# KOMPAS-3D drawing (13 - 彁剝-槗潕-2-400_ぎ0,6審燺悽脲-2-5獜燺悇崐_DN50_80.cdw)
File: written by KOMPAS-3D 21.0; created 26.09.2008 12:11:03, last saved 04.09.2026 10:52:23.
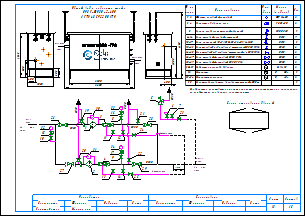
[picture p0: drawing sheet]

Sheets 1-2: A3, landscape

Document properties: Наименование: Макро:21; Автор: RaskoAdmin; Форматы листов документа: 2xA3; Полное имя файла: \\UR38nt01\Departments\КТО\КБ ПУРДГ\Заявки\Прайс-лист на типовые шкафы ГРПШ\ПРДГ_стандарт_20_03_2026\ПРДГ с РДНК\ПРДГ-ШУЭО-2-400_до0,6МПа_Рвых-2-5кПа_РДНК_DN50_80.cdw

Title block, sheet 1: Наименование: Пункт учета газа / ПУГ-Ш-400-Р / ЛГТИ.485922.001ТУ; designation: ЛГТИ.03.4411141; sheet number: 1; Количество листов документа: 2; organisation: ООО "ЭЛЬСТЕР Газэлектроника"; Форматы листов документа: A3; stored path: C:\Рабочие документы\Компас\ПУГ\Схема.cdw; Разработал: Устинов; Проверил: Кошкин; Утвердил: Кошкин
Title block, sheet 2: sheet number: 2; stored path: D:\Рабочие документы\Заявки\ПУРДГ\ПУРДГ-ШУЭО-2-100-Р 4411220.cdw; designation, second copy: ЛГТИ.03.4411141-

Views: Вид 1, Вид 2
Referenced files: wcvoit.frw
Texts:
  Normal
  Вход
  газа
  PDI
  Выход
  Р=     кПа
  DN80
  DN50
  DN20
  Импульс DN15
  ≥5DN
  HYSWLongFangSong
  № на
  схеме
  Усл.
  обозн.
  Марка
  (модель)
  Кол.
  Фильтр газовый фланцевый
  ФГ 16-50
  Регулятор давления газа
  РДНК-50
  Клапан предохранительный сбросной
  КПС DN20
  Кран шаровой газовый латунный
  DN15
  Кран кнопочный VE-РАСКО-НЗ-1,6-G1/2-М20
  Кран шаровой "под приварку" штуцерный DN20 PN16
  Кран шаровой "под приварку" штуцерный п/п DN15 PN16
  Кран шаровой фланцевый DN50 PN16
  Кран шаровой фланцевый DN80 PN16
  Индикатор перепада давления
  Delta 15
  Манометр
  Манометр-напоромер
  Электрообогреватель взрывозащищенный 400Вт
  0...     МПа
  0...     кПа
  Общий вид и габариты шкафа
  ПРДГ-ШУЭО-2-400
  Выход газа
  Вход газа
  Схема открывания дверей
  Р=        МПа
  logo-rasko-ge.png
  Предприятие изготовитель может заменять комплектующие на аналогичные,
  не ухудшающие заявленных характеристик.
  Должность
  Конструктор
  Фамилия
  Подпись
  Дата
  Согласовано
  Максимкин
  Лист
  Листов
  POLYLINE_STYLE_0.18_RGB_0_0_0
  POLYLINE_STYLE_0.50_RGB_0_0_0
  POLYLINE_STYLE_0.34_RGB_0_0_0
  PHANTOM_RGB_0_0_0_SC_1_THICK_0.18
  K5LT_THIN_RGB_0_0_0_THICK_0.18
  K5LT32769_RGB_0_0_0_THICK_0.18
  K5LT12_RGB_0_0_0_SC_1_THICK_0.18
  K5LT_DASHED_RGB_0_0_0_SC_1_THICK_0.18
  ACISOTGL_RGB_0_0_0_SC_0.8_THICK_0.25
  CONTINUOUS_RGB_0_127_31_THICK_0.3
  CONTINUOUS_RGB_0_0_255_THICK_0.35
  CONTINUOUS_RGB_255_0_0_THICK_0.35
  POLYLINE_STYLE_0.25_RGB_0_0_0
  CONTINUOUS_RGB_0_0_0_THICK_0.5
  POLYLINE_STYLE_0.35_RGB_0_0_255
  CONTINUOUS_RGB_0_0_0_THICK_0.4
  CONTINUOUS_RGB_0_0_0_THICK_0.35
  Без оформления
Dimensions and other numbers on the sheet: 1; 2; 3; 4; 5; 10; 27; 28; 29; 23; 8; 12; 19; 20; 21; 22; 25; 24; 30; 31; 15; 16; 26; 6; 7; 11; 14; 13; 33; 1, 2; 3, 4; 6-14; 9; 15-17; 18-23; 24-25; 26-27; 28-29; 30-31; 32; 33-34; 35; 400; 1050; 500; 305; 2300; 1565; 2600; 17; 34; 1000; 4130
